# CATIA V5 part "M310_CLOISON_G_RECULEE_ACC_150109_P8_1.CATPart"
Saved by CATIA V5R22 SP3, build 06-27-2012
Part number: CLOISON_G_RECULEE_150109_P8
Bounding box of the stored display mesh (mm): x -954.195 to -599.3, y -402.01 to -203.047, z -39.272 to 639.709
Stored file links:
  G:\piese costin 150109\M310_CLOISON_G_RECULEE_ACC_150109_P8_1.CATPart
  C:\Users\sys02\Desktop\piese D\150109\--.------.---.AA37688622.FL.P8_BRIN-AAS---------.----0002CAT.CATPART
  C:\Users\sys02\Desktop\ENVI_PRESENT\entorno con reservas\9813019380.CATPart
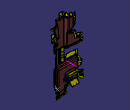
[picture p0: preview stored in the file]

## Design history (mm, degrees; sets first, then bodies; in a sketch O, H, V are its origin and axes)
AxisSystem1: origin (0, 0, 0), X (1, 0, 0), Y (0, 1, 0), Z (0, 0, 1)
StDynAnalysisRootNodeFeature1 "CATStDynAnalysisRootNodeName"
Set1 "GEOMETRY"
  DatumSurface1 to DatumSurface3
  MultiExtract1: ListOfMultiExtractConstraints MultiExtractConstraint face of DatumSurface2
  Extrapol1: ToExtrapol edge of MultiExtract1, Support MultiExtract1, Length 20
  Extrapol2: ToExtrapol edge of MultiExtract1, Support Extrapol1, Length 20
  Extrapol3: ToExtrapol edge of MultiExtract1, Support Extrapol2, Length 20
  MultiExtract2: ListOfMultiExtractConstraints MultiExtractConstraint face of DatumSurface3
  StUntrimFeature1 "CATStUntrimFeatureName": SpecToUntrim MultiExtract2
  Extrapol4: ToExtrapol edge of StUntrimFeature1, Support StUntrimFeature1, Length 3
  Extrapol5: ToExtrapol edge of StUntrimFeature1, Support Extrapol4, Length 10
  Extrapol6: ToExtrapol edge of StUntrimFeature1, Support Extrapol5, Length 10
  Extrapol7: ToExtrapol edge of StUntrimFeature1, Support Extrapol6, Length 10
  MultiExtract3: ListOfMultiExtractConstraints MultiExtractConstraint face of CloseSurface4
  CurvePar1: Offset edge of MultiExtract3, Support MultiExtract3, Offset2 0, Offset1 8
  Offset1: Offset Extrapol7, Length 5
  Plane1: type Normal, Curve Line3
  MultiExtract4: ListOfMultiExtractConstraints MultiExtractConstraint face of DatumSurface3
  MultiExtract5: ListOfMultiExtractConstraints MultiExtractConstraint face of DatumSurface3
  MultiExtract6: ListOfMultiExtractConstraints MultiExtractConstraint face of DatumSurface3
  StUntrimFeature2 "CATStUntrimFeatureName": SpecToUntrim MultiExtract4
  StUntrimFeature3 "CATStUntrimFeatureName": SpecToUntrim MultiExtract5
  StUntrimFeature4 "CATStUntrimFeatureName": SpecToUntrim MultiExtract6
  Extrapol8: ToExtrapol edge of StUntrimFeature2, Support StUntrimFeature2, Length 29
  Extrapol9: ToExtrapol edge of StUntrimFeature2, Support Extrapol8, Length 10
  Extrapol10: ToExtrapol edge of StUntrimFeature2, Support Extrapol9, Length 10
  Extrapol11: ToExtrapol edge of StUntrimFeature3, Support StUntrimFeature3, Length 10
  Extrapol12: ToExtrapol edge of StUntrimFeature3, Support Extrapol11, Length 10
  Blend1: StartLimit {blendlimit Curve edge of StUntrimFeature3, Support Extrapol12}, EndLimit {blendlimit Curve edge of StUntrimFeature2, Support Extrapol10}
  Extrapol13: ToExtrapol edge of StUntrimFeature3, Support Extrapol12, Length 3
  Extrapol14: ToExtrapol edge of StUntrimFeature4, Support StUntrimFeature4, Length 10
  Extrapol15: ToExtrapol edge of StUntrimFeature4, Support Extrapol14, Length 10
  Extrapol16: ToExtrapol edge of Offset1, Support Offset1, Length -10
  Join1: Elements (Extrapol10; Blend1; Extrapol13)
  Offset2: Offset Join1, Length 5
  Blend2: StartLimit {blendlimit Curve edge of Offset1}, EndLimit {blendlimit Curve edge of Offset2}
  Join2: Elements (Offset2; Blend2; Extrapol16)
  Fillet1: radius 5, on edge [face of Offset2 | face of Blend2]; edge [face of Offset1 | face of Blend2]
  Extrapol17: ToExtrapol edge of StUntrimFeature4, Support Extrapol15, Length 34
  Extrapol18: ToExtrapol edge of StUntrimFeature4, Support Extrapol17, Length 34
  Offset3: Offset Extrapol18, Length 5
  MultiExtract7: ListOfMultiExtractConstraints MultiExtractConstraint face of DatumSurface2
  MultiExtract8: ListOfMultiExtractConstraints MultiExtractConstraint face of DatumSurface2
  MultiExtract9: ListOfMultiExtractConstraints MultiExtractConstraint face of DatumSurface2
  StUntrimFeature5 "CATStUntrimFeatureName": SpecToUntrim MultiExtract9
  StUntrimFeature6 "CATStUntrimFeatureName": SpecToUntrim MultiExtract7
  StUntrimFeature7 "CATStUntrimFeatureName": SpecToUntrim MultiExtract8
  Extrapol19: ToExtrapol edge of Offset7, Support Offset7, Length 10
  Extrapol20: ToExtrapol edge of StUntrimFeature5, Support StUntrimFeature5, Length 10
  Extrapol21: ToExtrapol edge of StUntrimFeature7, Support StUntrimFeature7, Length 10
  Offset4: Offset Extrapol20, Length 5
  Trim1: Trimmed (Extrapol19; Offset6)
  Trim2: Trimmed (Extrapol21; Trim1)
  Fillet2: radius 1.5, on edge [face of Offset6 | face of Offset7]; edge [face of StUntrimFeature7 | face of Offset6]
  MultiExtract10: ListOfMultiExtractConstraints MultiExtractConstraint edge [face of DatumSurface2 | face of DatumSurface2]
  Split1: ToCut MultiExtract10, Cutting (vertex [face of MultiExtract10 | face of MultiExtract10]; vertex [face of MultiExtract10 | face of MultiExtract10])
  Sweep1: type Segment, GuideCrv Split1, Length1 3, Length2 3, Angle 3, DraftDirection Line3
  Extrapol22: ToExtrapol edge of Sweep1, Support Sweep1, Length 10
  Extrapol23: ToExtrapol edge of Sweep1, Support Extrapol22, Length 10
  Plane2: type Normal, Curve Line3
  Sketch1 on Plane2, origin (0, -255.047, 0), H (1, 0, 0), V (0, 0, 1)
    point P1 (-923.5217, 377.1007)
    point P2 (-847.9099, 507.5797)
  Point1: (0, 0, 0), relative to Sketch1.P2
  Point2: (0, 0, 0), relative to Sketch1.P1
  Translate1: ToTransfor Point1, Direction Line3, Length 103
  Translate2: ToTransfor Point2, Direction Line3, Length 103
  Point3: type Center, Curve edge [face of CloseSurface2 | face of CloseSurface2]
  Translate3: ToTransfor Extrapol23, FirstPoint Point3, SecondPoint Translate2
  Line1: type PtDir, RefPoint Translate2, Direction Line3, Start 0, End 20
  Rotate1: ToTransfor Translate3, Axis Line1, Angle 284
  Extrapol24: ToExtrapol edge of Rotate1, Support Rotate1, Length 10
  Extrapol25: ToExtrapol edge of Extrapol24, Support Extrapol24, Length 10
  Extrapol26: ToExtrapol edge of Extrapol24, Support Extrapol25, Length 10
  Plane3: type OffsetPt, RefPlane Plane2, RefPoint Translate2
  Symmetry1: ToTransfor Extrapol26, Reference Plane3
  Translate4: ToTransfor Symmetry1, FirstPoint Translate2, SecondPoint Translate1
  Sketch2 on Plane3, origin (0, -358.047, 0), H (1, 0, 0), V (0, 0, 1)
    line L1 (-946.3104, 406.3186) -> (-911.1251, 397.6334)
    arc A1 centre (-914.0208, 385.9024) radius 12.0831 from (-911.1251, 397.6334) to (-908.9389, 374.9399) cw
    line L2 (-908.9389, 374.9399) -> (-957.0341, 352.6442)
    line L3 (-957.0341, 352.6442) -> (-967.0956, 384.5557)
    line L4 (-967.0956, 384.5557) -> (-946.3104, 406.3186)
    line L5 (-898.9743, 508.102) -> (-831.044, 508.8939)
    arc A2 centre (-830.9389, 499.8784) radius 9.016 from (-831.044, 508.8939) to (-822.6455, 496.3417) cw
    line L6 (-822.6455, 496.3417) -> (-833.5773, 470.7073)
    line L7 (-833.5773, 470.7073) -> (-898.9743, 508.102)
    tangency: A1 L1, L2 A1, A2 L5, L6 A2
    fix: L5, L6
  Extrapol27: ToExtrapol edge of Offset6, Support Trim1, Length 10
  Offset5: Offset Extrapol21, Length 15
  Trim3: Trimmed (Extrapol27; Offset5)
  Sweep2: type Segment, GuideCrv edge of Offset4, GuideSurf Offset4, Length1 50, Length2 3, Angle 3
  Sweep3: type Segment, GuideCrv edge of Sweep2, GuideSurf Sweep2, Length1 50, Length2 3, Angle 3
  Offset6: Offset Sweep3, Length -1
  Offset7: Offset StUntrimFeature6, Length 1
  MultiExtract11: ListOfMultiExtractConstraints MultiExtractConstraint face of DatumSurface2
  MultiExtract12: ListOfMultiExtractConstraints MultiExtractConstraint face of DatumSurface2
  MultiExtract13: ListOfMultiExtractConstraints MultiExtractConstraint face of DatumSurface2
  MultiExtract14: ListOfMultiExtractConstraints MultiExtractConstraint face of DatumSurface2
  MultiExtract15: ListOfMultiExtractConstraints MultiExtractConstraint face of DatumSurface2
  MultiExtract16: ListOfMultiExtractConstraints MultiExtractConstraint face of DatumSurface2
  MultiExtract17: ListOfMultiExtractConstraints MultiExtractConstraint face of DatumSurface2
  MultiExtract18: ListOfMultiExtractConstraints MultiExtractConstraint face of DatumSurface2
  StUntrimFeature8 "CATStUntrimFeatureName": SpecToUntrim MultiExtract11
  StUntrimFeature9 "CATStUntrimFeatureName": SpecToUntrim MultiExtract12
  Extrapol28: ToExtrapol edge of StUntrimFeature9, Support StUntrimFeature9, Length 3
  Extrapol29: ToExtrapol edge of StUntrimFeature9, Support Extrapol28, Length 3
  Split2: ToCut Extrapol29, Cutting edge of StUntrimFeature8
  Split3: ToCut StUntrimFeature8, Cutting edge of MultiExtract11
  Split4: ToCut Split2, Cutting edge of MultiExtract12
  StUntrimFeature10 "CATStUntrimFeatureName": SpecToUntrim MultiExtract13
  StUntrimFeature11 "CATStUntrimFeatureName": SpecToUntrim MultiExtract14
  Extrapol30: ToExtrapol edge of StUntrimFeature10, Support StUntrimFeature10, Length 3
  Split5: ToCut Extrapol30, Cutting edge of StUntrimFeature11
  StUntrimFeature12 "CATStUntrimFeatureName": SpecToUntrim MultiExtract16
  Extrapol31: ToExtrapol edge of StUntrimFeature12, Support StUntrimFeature12, Length 3
  Join3: Elements (StUntrimFeature11; Split5)
  Join4: Elements (Split4; Split3)
  Trim4: Trimmed (Join3; Extrapol31)
  Trim5: Trimmed (Trim4; Join4)
  Plane4: type Normal, Curve edge [face of StUntrimFeature9 | face of StUntrimFeature12], RefPoint {point type OnCurve, Support edge [face of StUntrimFeature9 | face of StUntrimFeature12], Length 6.159}
  Plane5: type Normal, Curve edge [face of StUntrimFeature12 | face of StUntrimFeature8]
  Split6: ToCut Trim5, Cutting Plane5
  Split7: ToCut Split6, Cutting Plane4
  Fillet3: radius 0.5, on edge [face of StUntrimFeature12 | face of StUntrimFeature8]
  Plane6: type 3Points, Element1 vertex [face of StUntrimFeature11 | face of StUntrimFeature10], Element2 vertex [face of StUntrimFeature10], Element3 vertex [face of StUntrimFeature9]
  Plane7: type Offset, RefPlane Plane6, Offset 0.1, reversed
  Split8: ToCut Fillet3, Cutting Plane7
  Plane8: type Normal, Curve edge of Split8
  Split9: ToCut Split8, Cutting Plane8
  MultiExtract19: ListOfMultiExtractConstraints (MultiExtractConstraint face of DatumSurface1; MultiExtractConstraint face of DatumSurface1; MultiExtractConstraint face of DatumSurface1)
  Extrapol32: ToExtrapol edge of MultiExtract19, Support MultiExtract19, Length 20
  Extrapol33: ToExtrapol edge of MultiExtract19, Support Extrapol32, Length 3
  Offset8: Offset Extrapol53, Length 2
  Offset9: Offset Extrapol54, Length 2
  Offset10: Offset Extrapol33, Length 5
  Offset11: Offset Extrapol33, Length 5
  Split10: ToCut Offset19, Cutting Offset10
  Split11: ToCut Offset18, Cutting Offset10
  Split12: ToCut Offset8, Cutting Offset10
  Split13: ToCut Extrapol53, Cutting Offset10
  Split14: ToCut Split10, Cutting Offset11
  Split15: ToCut Split11, Cutting Offset11
  Split16: ToCut Split12, Cutting Offset11
  Split17: ToCut Split13, Cutting Offset11
  Plane9: type Normal, Curve edge of Offset10
  Split18: ToCut Offset10, Cutting Plane9
  Split19: ToCut Extrapol33, Cutting Plane9
  Split20: ToCut Offset11, Cutting Plane9
  Split21: ToCut Offset9, Cutting Split20
  Split22: ToCut Extrapol54, Cutting Split20
  Split23: ToCut Split21, Cutting Split18
  Split24: ToCut Split22, Cutting Split18
  Trim6: Trimmed (Split14; Split16)
  Trim7: Trimmed (Trim6; Split23)
  Trim8: Trimmed (Split24; Split15)
  Trim9: Trimmed (Trim8; Split17)
  Trim10: Trimmed (Split19; Trim7)
  Trim11: Trimmed (Trim9; Trim10)
  Extrapol34: ToExtrapol edge of Offset19, Support Offset19, Length 15
  Extrapol35: ToExtrapol edge of Offset18, Support Offset18, Length 15
  Extrapol36: ToExtrapol edge of Offset19, Support Extrapol34, Length 15
  Extrapol37: ToExtrapol edge of Offset18, Support Extrapol35, Length 15
  MultiExtract20: ListOfMultiExtractConstraints MultiExtractConstraint face of DatumSurface1
  StUntrimFeature13 "CATStUntrimFeatureName": SpecToUntrim MultiExtract20
  Extrapol38: ToExtrapol edge of StUntrimFeature13, Support StUntrimFeature13, Length 15
  Extrapol39: ToExtrapol edge of StUntrimFeature13, Support Extrapol38, Length 15
  Offset12: Offset Extrapol39, Length 6
  Offset13: Offset Extrapol39, Length 6
  Offset14: Offset Offset12, Length 2
  MultiExtract21: ListOfMultiExtractConstraints MultiExtractConstraint face of DatumSurface1
  StUntrimFeature14 "CATStUntrimFeatureName": SpecToUntrim MultiExtract21
  Intersect1: ToIntersect1 StUntrimFeature14, ToIntersect2 Offset13
  Sweep4: type Segment, GuideCrv Intersect1, Length1 50, Length2 3, Angle 3, DraftDirection Line3
  Offset15: Offset Sweep4, Length 2
  MultiExtract22: ListOfMultiExtractConstraints (MultiExtractConstraint face of DatumSurface1; MultiExtractConstraint face of DatumSurface1; MultiExtractConstraint face of DatumSurface1; MultiExtractConstraint face of DatumSurface1; MultiExtractConstraint face of DatumSurface1)
  Extrapol40: ToExtrapol edge of MultiExtract22, Support MultiExtract22, Length 15
  Plane10: type Normal, Curve edge of MultiExtract22
  Split25: ToCut Sweep4, Cutting Plane10
  Split26: ToCut Offset15, Cutting Plane10
  Split27: ToCut Offset14, Cutting Plane10
  Split28: ToCut Offset12, Cutting Plane10
  Split29: ToCut Extrapol40, Cutting Plane10
  Trim12: Trimmed (Extrapol36; Split27)
  Trim13: Trimmed (Trim12; Split26)
  Extrapol41: ToExtrapol edge of Offset15, Support Trim13, Length 15
  Extrapol42: ToExtrapol edge of Sweep4, Support Split25, Length 15
  Trim14: Trimmed (Extrapol41; Split29)
  Trim15: Trimmed (Extrapol37; Split28)
  Trim16: Trimmed (Trim15; Extrapol42)
  Trim17: Trimmed (Trim16; Trim14)
  Fillet4: radius 2, on edge [face of Offset19 | face of Offset14]
  Fillet5: radius 2, on edge [face of Offset15 | face of Offset19]
  Fillet6: radius 4, on edge [face of Offset18 | face of Sweep4]
  Fillet7: radius 4, on edge [face of Offset18 | face of Offset12]
  MultiExtract23: ListOfMultiExtractConstraints (MultiExtractConstraint face of DatumSurface2; MultiExtractConstraint face of DatumSurface2; MultiExtractConstraint face of DatumSurface2)
  Plane11: type Normal, Curve edge of MultiExtract23, RefPoint vertex [face of DatumSurface2]
  Split30: ToCut MultiExtract23, Cutting Plane11
  Extrapol43: ToExtrapol edge of MultiExtract23, Support Split30, Length 15
  Extrapol44: ToExtrapol edge of Split30, Support Extrapol43, Length 20
  Extrapol45: ToExtrapol edge of MultiExtract23, Support Extrapol44, Length 20
  Offset16: Offset Extrapol45, Length 1.8
  Plane12: type Normal, Curve edge of Offset16, RefPoint {point type OnCurve, Support edge of Offset16, Length 13.12}
  Intersect2: ToIntersect1 Offset16, ToIntersect2 Plane12
  Sweep5: type Segment, GuideCrv Intersect2, Length1 50, Length2 3, Angle 3, DraftDirection (1, 0, 0)
  Trim18: Trimmed (Offset16; Sweep5)
  MultiExtract24: ListOfMultiExtractConstraints MultiExtractConstraint face of DatumSurface2
  StUntrimFeature15 "CATStUntrimFeatureName": SpecToUntrim MultiExtract24
  Extrapol46: ToExtrapol edge of StUntrimFeature15, Support StUntrimFeature15, Length 20
  Offset17: Offset Offset19, Length 13.8
  Extrapol47: ToExtrapol edge of Offset17, Support Offset17, Length 50
  Trim19: Trimmed (Trim18; Extrapol47)
  Point4: type OnCurve, Support edge of Offset16, Length 8.5
  Line2: type PtDir, RefPoint Point4, Direction (1, 0, 0), Start -27, End 20
  Sweep6: type Segment, GuideCrv Line2, Length1 50, Length2 3, Angle 20, DraftDirection (0, 0, 1)
Set2 "DRAFT DIR"
  Line3: stored without definition
Set3 "Construction"
  Point5: stored without definition
  Point6: stored without definition
  MultiExtract25: ListOfMultiExtractConstraints MultiExtractConstraint face of DatumSurface1
  MultiExtract26: ListOfMultiExtractConstraints MultiExtractConstraint face of DatumSurface1
  StUntrimFeature16 "CATStUntrimFeatureName": SpecToUntrim MultiExtract25
  StUntrimFeature17 "CATStUntrimFeatureName": SpecToUntrim MultiExtract26
  Extrapol48: ToExtrapol edge of StUntrimFeature16, Support StUntrimFeature16, Length 5
  Extrapol49: ToExtrapol edge of StUntrimFeature17, Support StUntrimFeature17, Length 5
  Extrapol50: ToExtrapol edge of StUntrimFeature16, Support Extrapol48, Length 20
  Extrapol51: ToExtrapol edge of StUntrimFeature17, Support Extrapol49, Length 20
  Offset18: Offset Extrapol50, Length 7
  Offset19: Offset Extrapol51, Length 7
  MultiExtract27: ListOfMultiExtractConstraints MultiExtractConstraint face of DatumSurface1
  StUntrimFeature18 "CATStUntrimFeatureName": SpecToUntrim MultiExtract27
  Extrapol52: ToExtrapol edge of StUntrimFeature18, Support StUntrimFeature18, Length 20
  Offset20: Offset Extrapol52, Length 28
  Extrapol53: ToExtrapol edge of Offset20, Support Offset20, Length 20
  MultiExtract28: ListOfMultiExtractConstraints MultiExtractConstraint face of DatumSurface1
  StUntrimFeature19 "CATStUntrimFeatureName": SpecToUntrim MultiExtract28
  Offset21: Offset StUntrimFeature19, Length 8
  Extrapol54: ToExtrapol edge of Offset21, Support Offset21, Length 20
  MultiExtract29: ListOfMultiExtractConstraints MultiExtractConstraint face of ThickSurface1
  StUntrimFeature20 "CATStUntrimFeatureName": SpecToUntrim MultiExtract29
  Extrapol55: ToExtrapol edge of StUntrimFeature20, Support StUntrimFeature20, Length 5
  Trim20: Trimmed (Offset16; Sweep6)
  Trim21: Trimmed (Extrapol55; Trim20)
  MultiExtract30: ListOfMultiExtractConstraints (MultiExtractConstraint face of StUntrimFeature10; MultiExtractConstraint face of StUntrimFeature11)
  Extrapol56: ToExtrapol edge of Split6, Support MultiExtract30, Length 5
  MultiExtract31: ListOfMultiExtractConstraints MultiExtractConstraint face of DatumSurface2
  StUntrimFeature21 "CATStUntrimFeatureName": SpecToUntrim MultiExtract31
  Extrapol57: ToExtrapol edge of StUntrimFeature21, Support StUntrimFeature21, Length 20
  Extrapol58: ToExtrapol edge of StUntrimFeature21, Support Extrapol57, Length 20
  Offset22: Offset Extrapol58, Length 3
  MultiExtract32: ListOfMultiExtractConstraints (MultiExtractConstraint face of DatumSurface2; MultiExtractConstraint face of DatumSurface2; MultiExtractConstraint face of DatumSurface2)
  Plane13: type Normal, Curve edge of MultiExtract32, RefPoint vertex [face of DatumSurface2]
  Split31: ToCut MultiExtract32, Cutting Plane13
  Extrapol59: ToExtrapol edge of Split31, Support Split31, Length 20
  MultiExtract33: ListOfMultiExtractConstraints (MultiExtractConstraint face of DatumSurface2; MultiExtractConstraint face of DatumSurface2; MultiExtractConstraint face of DatumSurface2; MultiExtractConstraint face of DatumSurface2; MultiExtractConstraint face of DatumSurface2; MultiExtractConstraint face of DatumSurface2; MultiExtractConstraint face of DatumSurface2)
  Trim22: Trimmed (MultiExtract33; Sweep6)
  Plane14: type Normal, Curve edge of MultiExtract33, RefPoint vertex [face of DatumSurface2]
  Plane15: type Offset, RefPlane Plane14, Offset 1, reversed
  Split32: ToCut Trim22, Cutting Plane15
  CurvePar2: Offset edge of MultiExtract33, Support Split32, Offset2 0, Offset1 2
  Split33: ToCut Split32, Cutting CurvePar2
  Trim23: Trimmed (Extrapol55; Sweep6)
  CurvePar3: Offset edge of StUntrimFeature20, Support Trim23, Offset2 0, Offset1 2
  Split34: ToCut Trim23, Cutting CurvePar3
  Offset23: Offset Sweep5, Length 1.8
  Trim24: Trimmed (Offset23; Split34)
  MultiExtract34: ListOfMultiExtractConstraints MultiExtractConstraint face of Pocket4 from Sketch4.L3
  MultiExtract35: ListOfMultiExtractConstraints MultiExtractConstraint face of Pocket4 from Sketch4.L4
  MultiExtract36: ListOfMultiExtractConstraints MultiExtractConstraint start face of Pocket4
  Offset24: Offset MultiExtract36, Length 5
  StUntrimFeature22 "CATStUntrimFeatureName": SpecToUntrim MultiExtract35
  Extrapol60: ToExtrapol edge of StUntrimFeature22, Support StUntrimFeature22, Length 8
  StUntrimFeature23 "CATStUntrimFeatureName": SpecToUntrim Offset24
  Extrapol61: ToExtrapol edge of StUntrimFeature23, Support StUntrimFeature23, Length 8
  Extrapol62: ToExtrapol edge of StUntrimFeature23, Support Extrapol61, Length 8
  Extrapol63: ToExtrapol edge of MultiExtract34, Support MultiExtract34, Length 8
  Extrapol64: ToExtrapol edge of StUntrimFeature22, Support Extrapol60, Length 8
  Extrapol65: ToExtrapol edge of MultiExtract34, Support Extrapol63, Length 8
  Offset25: Offset Extrapol62, Length 6
  CurvePar4: Offset edge of StUntrimFeature22, Support Extrapol64, Offset2 0, Offset1 22
  Sweep7: type Segment, GuideCrv CurvePar4, GuideSurf Extrapol64, Length1 50, Length2 3, Angle 15
  Trim25: Trimmed (Extrapol64; Sweep7)
  Trim26: Trimmed (Offset25; Extrapol65)
  Trim27: Trimmed (Trim25; Trim26)
  DatumSurface4
  Set4
    DatumSurface5
Body1 (main body)
Body2 "HARD"
  CloseSurface1: CloseElement DatumSurface1
  FaceFillet1: ConicRatio 0.5, Face1 face of CloseSurface1, Face2 face of CloseSurface1, Radius 15
  FaceFillet2: ConicRatio 0.5, Face1 face of CloseSurface1, Face2 face of CloseSurface1, Radius 17
  Split35: SplitPlane Fillet7
  Fillet8: radius 2, on edge [face of CloseSurface1 | face of Split35]
  Fillet9: radius 4, on edge [face of CloseSurface1 | face of Split35]
  Fillet10: radius 2, on edge [face of CloseSurface1 | face of Split35]
  Fillet11: radius 4, on edge [face of Split35 | face of CloseSurface1]
Body3 "GOMA-1"
  Body4 "GOMA1"
    CloseSurface2: CloseElement DatumSurface2
    Split36: SplitPlane Extrapol3
    Fillet12: radius 1, on edge [face of Split36 | face of CloseSurface2]
    Sketch3 on face of CloseSurface1, origin (-58.8491, -465.5514, 16.3655), H (-0.9921, 0.1254, 0), V (0.0044, 0.0346, 0.9994)
      line L1 (792.918, 465.9051) -> (771.7653, 453.4804)
      arc A1 centre (772.7418, 451.8178) radius 1.9282 from (771.7653, 453.4804) to (773.7184, 450.1552) ccw
      line L2 (773.7184, 450.1552) -> (794.8712, 462.5799)
      line L3 (794.8712, 462.5799) -> (792.918, 465.9051)
      tangency: A1 L1, L2 A1
      perpendicularity: L3 L1, L2 L3
    Pocket1: profile Sketch3, direction along Line3, length 20
    Draft1: Angle 3, Neutral face of CloseSurface2, PullDir Line3, SupportToDraft face of Pocket1 from Sketch3.A1
    Fillet13: radius 1, on edge [face of Pocket1 from Sketch3.L2 | face of CloseSurface2]
    Pocket2: profile Sketch7, direction (0, 1, 0), length 20, opposite side length 349, thin wall 3.5
    RemoveFace1: RemoveFaces (face of CloseSurface2; face of CloseSurface2; face of CloseSurface2; face of CloseSurface2)
    RemoveFace2: RemoveFaces (face of CloseSurface2; face of CloseSurface2; face of CloseSurface2; face of CloseSurface2)
    Draft2: Angle 0.5, Neutral face of CloseSurface2, PullDir Line3, SupportToDraft (face of Pocket2; face of Pocket2; face of Pocket2)
    Split37: SplitPlane Fillet2
    Fillet14: radius 0.4, on edge [face of CloseSurface2 | face of Split37]
    Draft3: Angle 0.5, Neutral (face of CloseSurface2; face of CloseSurface2; face of CloseSurface2; face of CloseSurface2; face of CloseSurface2), PullDir Line3, SupportToDraft (face of Pocket2; face of Pocket2; face of Pocket2)
    Fillet15: radius 1.5, on edge [face of Pocket2 | face of Pocket2] (x2)
    Fillet16: radius 1, on edge [face of Pocket2 | face of CloseSurface2]
    Fillet17: radius 1, on edge [face of Pocket2 | face of CloseSurface2]
    Draft4: Angle 3, Neutral (face of CloseSurface2; face of CloseSurface2), PullDir Line3, SupportToDraft (face of Pocket2; face of Pocket2; face of Pocket2)
    Fillet18: radius 1.5, on edge [face of Pocket2 | face of Pocket2] (x2)
    Fillet19: radius 1, on edge [face of Pocket2 | face of CloseSurface2]
    FaceFillet3: ConicRatio 0.5, Face1 face of CloseSurface2, Face2 face of CloseSurface2, Radius 15
    FaceFillet4: ConicRatio 0.5, Face1 face of CloseSurface2, Face2 face of CloseSurface2, Radius 17
    RemoveFace3: RemoveFaces (face of CloseSurface2; face of CloseSurface2; face of CloseSurface2; face of CloseSurface2; face of CloseSurface2; face of CloseSurface2; face of CloseSurface2; face of CloseSurface2; face of CloseSurface2; face of CloseSurface2)
    Pocket3: profile Sketch2, direction (0, 1, 0), length 20, mirrored extent
    Draft5: Angle 3, Neutral face of CloseSurface2, PullDir Line3, SupportToDraft face of Pocket3 from Sketch2.L6
    Fillet20: radius 1, on edge [face of Pocket3 from Sketch2.L6 | face of CloseSurface2]
    Fillet21: radius 1, on edge [face of Pocket3 from Sketch2.L6 | face of CloseSurface2]
    Draft6: Angle 3, Neutral face of CloseSurface2, PullDir Line3, SupportToDraft face of Pocket3 from Sketch2.L1
    Fillet22: radius 1, on edge [face of Pocket3 from Sketch2.L1 | face of CloseSurface2]
    SewSurface1: SplitPlane Split9
    Body5
      CloseSurface3: CloseElement DatumSurface1
      Split38: SplitPlane Fillet7
    Add1: tool Body5
    Fillet23: radius 2, on edge [face of Split38 | face of CloseSurface2]
    Fillet24: radius 4, on edge [face of Split38 | face of CloseSurface2]
    Fillet25: radius 2, on edge [face of Split38 | face of CloseSurface2]
    Fillet26: radius 4, on edge [face of CloseSurface2 | face of Split38]
    Sketch4 on face of CloseSurface2, origin (0, -32.9733, 629.1681), H (1, 0, 0), V (0, 0.9986, 0.0523)
      line L1 (-798.2832, -308.4571) -> (-782.8998, -308.4571)
      line L2 (-782.8998, -308.4571) -> (-782.8998, -325.121)
      line L3 (-782.8998, -325.121) -> (-798.2832, -325.121)
      line L4 (-798.2832, -325.121) -> (-798.2832, -308.4571)
      horizontal: L1 H, L3 H
      vertical: L2 V, L4 V
    Pocket4: profile Sketch4, direction (0, -0.0523, 0.9986), length 34
    RemoveFace4: RemoveFaces (face of CloseSurface2; face of CloseSurface2)
    Thickness1: Face face of Pocket4 from Sketch4.L3, Thickness 3
    RemoveFace5: RemoveFaces face of CloseSurface2
    Draft7: Angle 10, Neutral start face of Pocket4, PullDir Z axis, SupportToDraft face of Pocket4 from Sketch4.L3
    Thickness2: Face face of Pocket4 from Sketch4.L3, Thickness 3
    Fillet27: radius 5, on edge [face of Pocket4 from Sketch4.L3 | face of CloseSurface2]
    Draft8: Angle 7, Neutral start face of Pocket4, PullDir Z axis, SupportToDraft face of Pocket4 from Sketch4.L4
    Split39: SplitPlane DatumSurface4
    Draft9: Angle 3, Neutral (face of CloseSurface3; face of CloseSurface3), PullDir Line3, SupportToDraft face of Split39
    Draft10: Angle 3, Neutral (face of CloseSurface2; face of CloseSurface2; face of SewSurface1; face of CloseSurface2; face of CloseSurface3), PullDir Line3, SupportToDraft face of Split39
    Draft11: Angle 3, Neutral (face of SewSurface1; face of SewSurface1), PullDir Line3, SupportToDraft start face of Pocket4
    Draft12: Angle 3, Neutral face of CloseSurface2, PullDir Line3, SupportToDraft face of Split39
    Fillet28: radius 5, on edge [face of Split39 | start face of Pocket4]
    Fillet29: radius 6, on edge [face of Split39 | face of SewSurface1]
    Fillet30: radius 5, on edge [face of Fillet28 | face of Split39]
    Fillet31: radius 2.5, on edge [face of Split39 | face of Split39]
    Fillet32: radius 10, on edge [face of Split39 | face of Pocket4 from Sketch4.L3]
    Fillet33: radius 1.5, on edge [face of Split39 | face of Split39]
    Fillet34: radius 0.45, on edge [face of Split39 | face of CloseSurface2]
    Sketch5 on face of CloseSurface2, origin (0, -384.953, 0), H (-1, 0, 0), V (0, 0, 1)
      line L1 (795.4685, 311.4472) -> (766.4116, 311.4472)
      line L2 (766.4116, 285.4847) -> (795.4685, 285.4847)
      line L3 (766.4583, 264.4207) -> (795.5153, 264.4207)
      horizontal: L1 H, L2 H, L3 H
    Pocket5: profile Sketch5, direction (0, -1, 0), length 34, mirrored extent, thin wall 3.7
    Draft13: Angle 3, Neutral face of CloseSurface2, PullDir Line3, SupportToDraft (face of Pocket5; face of Pocket5; face of Pocket5; face of Pocket5; face of Pocket5; face of Pocket5; face of Pocket5; face of Pocket5; face of Pocket5)
    Fillet35: radius 1.5, on edge [face of Pocket5 | face of Pocket5] (x6)
    Fillet36: radius 1, on edge [face of CloseSurface2 | face of Pocket5]; edge [face of Pocket5 | face of CloseSurface2] (x2)
  Add2: tool Body4
  Sketch6 on face of Pocket2, origin (-692.911, -6.0778, 70.1468), H (-0.0088, 1, 0), V (0.1007, 0.0009, 0.9949)
    line L1 (-355.6605, -81.2785) -> (-361.9571, -83.6492)
    line L2 (-361.9571, -83.6492) -> (-361.1096, -91.4124)
    line L3 (-361.1096, -91.4124) -> (-354.904, -89.5192)
    line L4 (-354.904, -89.5192) -> (-355.6605, -81.2785)
  Pocket6: profile Sketch6, direction (-0.9949, -0.0087, 0.1007), up to face of Pocket2
  Fillet37: radius 1.5, on edge [face of Pocket2 | face of Pocket6 from Sketch6.L1]; edge [face of Pocket6 from Sketch6.L1 | face of Pocket2]
  Fillet38: radius 1, on edge [face of Pocket2 | face of CloseSurface2]
  Split40: SplitPlane Trim3
  RemoveFace6: RemoveFaces (face of CloseSurface2; face of CloseSurface2), deactivated
  Thickness3: Face face of Split40, Thickness 1
  Fillet39: radius 1, on edge [face of Split40 | face of Split40]
  Fillet40: radius 3, on edge [face of Split40 | face of Split40]
  Fillet41: radius 0.4, on edge [face of Split40 | face of CloseSurface2]
  RemoveFace7: RemoveFaces (face of CloseSurface2; face of CloseSurface2; face of CloseSurface2; face of CloseSurface2; face of CloseSurface2; face of CloseSurface2; face of CloseSurface2; face of CloseSurface2; face of CloseSurface2; face of CloseSurface2; face of CloseSurface2; face of CloseSurface2; face of CloseSurface2; face of CloseSurface2; face of CloseSurface2; face of CloseSurface2; face of CloseSurface2; face of CloseSurface2; face of CloseSurface2; face of CloseSurface2; face of CloseSurface2; face of CloseSurface2; face of CloseSurface2; face of CloseSurface2; face of CloseSurface2; face of CloseSurface2; face of CloseSurface2; face of CloseSurface2; face of CloseSurface2; face of CloseSurface2; face of CloseSurface2)
  RemoveFace8: RemoveFaces (face of CloseSurface2; face of CloseSurface2; face of CloseSurface2; face of CloseSurface2; face of CloseSurface2; face of CloseSurface2; face of CloseSurface2; face of CloseSurface2; face of CloseSurface2; face of CloseSurface2)
  Split41: SplitPlane DatumSurface5
  Fillet42: radius 0.5, on edge [face of Split41 | face of Split41] (x2); edge [face of Split41 | face of CloseSurface2] (x2)
  Fillet43: radius 0.5, on edge [face of CloseSurface2 | face of CloseSurface2]
Body6 "GOMA2"
  CloseSurface4: CloseElement DatumSurface3
  Sketch7 on Plane1, origin (0, -255.047, 0), H (1, 0, 0), V (0, 0, 1)
    line L1 (-677.701, 196.2054) -> (-659.8584, 196.2054)
    point P1 (-677.701, 196.2054)
    line L2 (-677.701, 173.0909) -> (-658.5528, 173.0909)
    point P3 (-677.701, 173.0909)
    line L3 (-677.701, 149.2784) -> (-658.5528, 149.2784)
    point P5 (-677.701, 149.2784)
    line L4 (-677.701, 125.6627) -> (-659.4424, 125.6627)
    point P7 (-677.701, 125.6627)
    line L5 (-677.701, 102.2412) -> (-659.4424, 102.2412)
    point P9 (-677.701, 102.2412)
    line L6 (-677.701, 78.9696) -> (-658.4034, 78.9696)
    point P11 (-677.701, 78.9696)
    line L7 (-703.5012, 293.2072) -> (-679.2587, 293.2072)
    line L8 (-702.9385, 268.6379) -> (-679.2587, 268.6379)
    line L9 (-703.1518, 243.4506) -> (-677.9908, 243.4506)
    line L10 (-703.0854, 220.2014) -> (-678.8353, 220.2014)
    line L11 (-703.633, 318.0093) -> (-685.3015, 318.0093)
    line L12 (-703.2807, 343.4559) -> (-682.4467, 343.4559)
    line L13 (-676.7986, 362.7195) -> (-659.2946, 362.7195)
    point P25 (-676.7986, 362.7195)
    line L14 (-676.7986, 407.856) -> (-656.218, 407.856)
    point P27 (-676.7986, 407.856)
    line L15 (-699.1858, -40.2988) -> (-696.8214, -16.9959)
    line L16 (-676.7986, 391.5685) -> (-656.8031, 391.5685)
    point P31 (-676.7986, 391.5685)
    line L17 (-676.7986, 376.1327) -> (-656.8031, 376.1327)
    point P33 (-676.7986, 376.1327)
    reference projected line E1 (-681.7986, 374.3899) -> (-681.7986, 409.943) from edge [face of CloseSurface4 | face of CloseSurface4]
    construction line L18 (-676.7986, 391.5685) -> (-676.7986, 381.3489)
    construction line L19 (-677.701, 200.2971) -> (-677.701, 186.7452)
    reference projected line E2 (-682.701, 193.2991) -> (-682.701, 77.7855) from edge [face of CloseSurface4 | face of CloseSurface4]
    line L20 (-700.7139, 500.3451) -> (-689.9854, 489.4459)
    line L21 (-689.9854, 489.4459) -> (-699.0717, 480.5019)
    distance E1 P31 = 5
    distance E2 L19 = 5
    horizontal: L1 H, L2 H, L3 H, L4 H, L5 H, L6 H, L7 H, L8 H, L9 H, L10 H, L11 H, L12 H, L13 H, L14 H, L16 H, L17 H
    vertical: L18 V, L19 V
    coincidence: L18 P27, P33 L18, P25 L18, P1 L19, L19 P3, P5 L19, P7 L19, P9 L19, P11 L19
    fix: L15
    perpendicularity: L21 L20
  Pocket7: profile Sketch7, direction (0, 1, 0), length 20, opposite side length 311, thin wall 3.5
  Split42: SplitPlane Offset3, deactivated
  Split43: SplitPlane Fillet1, deactivated
  RemoveFace9: RemoveFaces (face of CloseSurface4; face of CloseSurface4; face of CloseSurface4)
  RemoveFace10: RemoveFaces (face of CloseSurface4; face of CloseSurface4; face of CloseSurface4; face of CloseSurface4; face of CloseSurface4; face of CloseSurface4)
  Draft14: Angle 3, Neutral face of CloseSurface4, PullDir Line3, SupportToDraft (face of Pocket7; face of Pocket7; face of Pocket7; face of Pocket7; face of Pocket7; face of Pocket7; face of Pocket7; face of Pocket7; face of Pocket7; face of Pocket7; face of Pocket7; face of Pocket7)
  Fillet44: radius 5, on edge [face of Pocket7 | face of CloseSurface4]
  Fillet45: radius 1.5, on edge [face of Pocket7 | face of Pocket7] (x8)
  Fillet46: radius 1, on edge [face of Pocket7 | face of CloseSurface4] (x3)
  Fillet47: radius 0.49, on edge [face of Pocket7 | face of CloseSurface4]
  RemoveFace11: RemoveFaces (face of CloseSurface4; face of CloseSurface4; face of CloseSurface4)
  RemoveFace12: RemoveFaces (face of CloseSurface4; face of CloseSurface4; face of CloseSurface4)
  RemoveFace13: RemoveFaces (face of CloseSurface4; face of CloseSurface4; face of CloseSurface4; face of CloseSurface4)
  RemoveFace14: RemoveFaces (face of CloseSurface4; face of CloseSurface4; face of CloseSurface4; face of CloseSurface4)
  RemoveFace15: RemoveFaces (face of CloseSurface4; face of CloseSurface4; face of CloseSurface4; face of CloseSurface4; face of CloseSurface4; face of CloseSurface4)
  RemoveFace16: RemoveFaces (face of CloseSurface4; face of CloseSurface4; face of CloseSurface4)
  RemoveFace17: RemoveFaces (face of CloseSurface4; face of CloseSurface4; face of CloseSurface4; face of CloseSurface4)
  RemoveFace18: RemoveFaces (face of CloseSurface4; face of CloseSurface4; face of CloseSurface4; face of CloseSurface4)
  RemoveFace19: RemoveFaces (face of CloseSurface4; face of CloseSurface4; face of CloseSurface4)
  RemoveFace20: RemoveFaces (face of CloseSurface4; face of CloseSurface4; face of CloseSurface4; face of CloseSurface4; face of CloseSurface4; face of CloseSurface4; face of CloseSurface4)
  RemoveFace21: RemoveFaces (face of CloseSurface4; face of CloseSurface4; face of CloseSurface4; face of CloseSurface4; face of CloseSurface4)
  RemoveFace22: RemoveFaces (face of CloseSurface4; face of CloseSurface4; face of CloseSurface4; face of CloseSurface4)
  Fillet48: radius 1.5, on edge [face of Pocket7 | face of Pocket7] (x12)
  Fillet49: radius 1, on edge [face of Pocket7 | face of CloseSurface4] (x4)
  Fillet50: radius 1.1, on edge [face of Pocket7 | face of CloseSurface4]
  Fillet51: radius 1.1, on edge [face of Pocket7 | face of CloseSurface4]
  Fillet52: radius 0.99, on edge [face of CloseSurface4 | face of Pocket7]
  RemoveFace23: RemoveFaces (face of CloseSurface4; face of CloseSurface4; face of CloseSurface4; face of CloseSurface4)
  RemoveFace24: RemoveFaces (face of CloseSurface4; face of CloseSurface4; face of CloseSurface4; face of CloseSurface4)
  RemoveFace25: RemoveFaces (face of CloseSurface4; face of CloseSurface4; face of CloseSurface4; face of CloseSurface4; face of CloseSurface4; face of CloseSurface4)
  RemoveFace26: RemoveFaces (face of CloseSurface4; face of CloseSurface4; face of CloseSurface4)
  RemoveFace27: RemoveFaces (face of CloseSurface4; face of CloseSurface4; face of CloseSurface4; face of CloseSurface4)
  RemoveFace28: RemoveFaces (face of CloseSurface4; face of CloseSurface4; face of CloseSurface4; face of CloseSurface4)
  RemoveFace29: RemoveFaces (face of CloseSurface4; face of CloseSurface4; face of CloseSurface4; face of CloseSurface4)
  RemoveFace30: RemoveFaces (face of CloseSurface4; face of CloseSurface4; face of CloseSurface4; face of CloseSurface4)
  RemoveFace31: RemoveFaces (face of CloseSurface4; face of CloseSurface4; face of CloseSurface4; face of CloseSurface4)
  RemoveFace32: RemoveFaces (face of CloseSurface4; face of CloseSurface4; face of CloseSurface4; face of CloseSurface4)
  RemoveFace33: RemoveFaces (face of CloseSurface4; face of CloseSurface4; face of CloseSurface4; face of CloseSurface4)
  Draft15: Angle 3, Neutral face of CloseSurface4, PullDir Line3, SupportToDraft (face of Pocket7; face of Pocket7; face of Pocket7; face of Pocket7; face of Pocket7; face of Pocket7; face of Pocket7; face of Pocket7; face of Pocket7; face of Pocket7; face of Pocket7; face of Pocket7; face of Pocket7; face of Pocket7; face of Pocket7; face of Pocket7; face of Pocket7)
  Draft16: Angle 3, Neutral face of CloseSurface4, PullDir Line3, SupportToDraft face of Pocket7
  Fillet53: radius 1.5, on edge [face of Pocket7 | face of Pocket7] (x12)
  Fillet54: radius 1, on edge [face of CloseSurface4 | face of Pocket7]
  Fillet55: radius 1, on edge [face of Pocket7 | face of CloseSurface4] (x5)
Body7
  ThickSurface1: BotOffset 0, Surface Trim19, TopOffset 1.8, deactivated
  Split44: SplitPlane Extrapol46, deactivated
Body8 "Résultat de S,06073-,B5A---,---PLASTI-RIVET--,CA-2760,S-,00,------------,070110,RG.2\\Pointe mobile"
  Solid1: solid without history
Body9 "Résultat de S,06073-,B5A---,---PLASTI-RIVET--,CA-2760,S-,00,------------,070110,RG.2\\Corps"
  Solid2: solid without history
Body10 "Résultat de S,06073-,B5A---,---PLASTI-RIVET--,CA-2760,S-,00,------------,070110,RG.2\\Pointe mobile"
  Solid3: solid without history
Body11 "Résultat de S,06073-,B5A---,---PLASTI-RIVET--,CA-2760,S-,00,------------,070110,RG.2\\Corps"
  Solid4: solid without history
